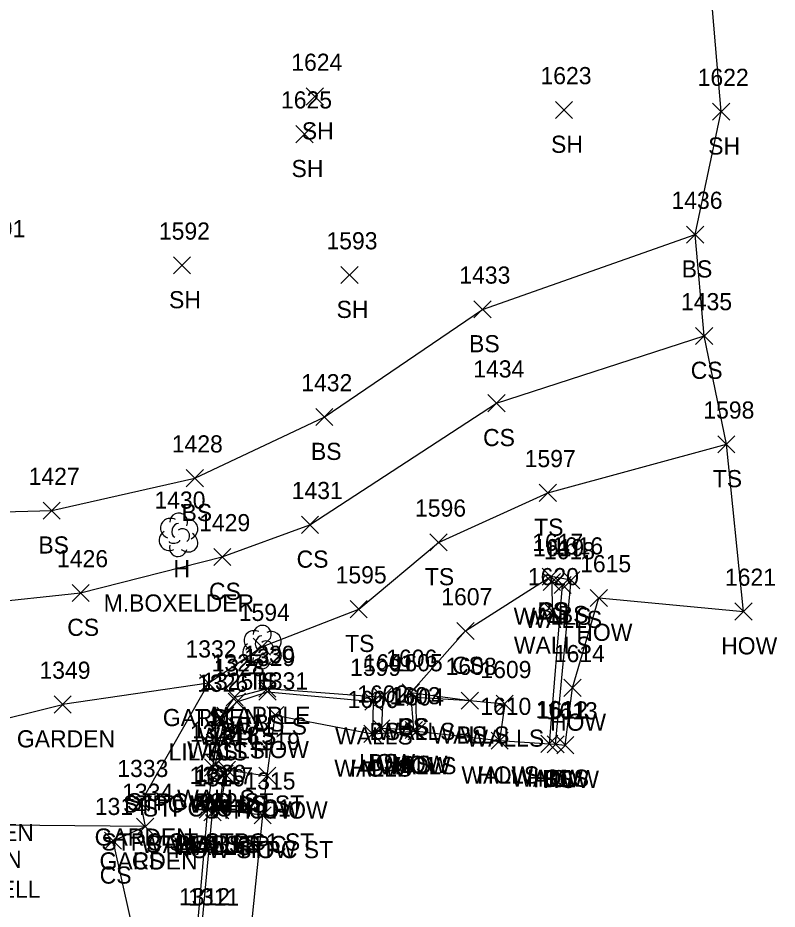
# Model space of a CAD drawing. Extents: x 1459992 to 1461532, y 647785 to 648535.
# Drawn here: x 1461426.2 to 1461514.7, y 648133.4 to 648237.3 of the extents above; entities that cross this region are included whole.
import ezdxf

# ---------------------------------------------------------------- set-up
doc = ezdxf.new("R2010")
doc.units = 0
for name, color, linetype in [('L_A', 7, 'Continuous'), ('L_C', 7, 'Continuous'), ('L_I', 7, 'Continuous'), ('L_TIC', 7, 'Continuous'), ('LAPB', 7, 'Continuous'), ('LBC', 7, 'Continuous'), ('LBF', 7, 'Continuous'), ('LELB', 7, 'Continuous'), ('LSOGP', 7, 'Continuous'), ('LTD', 7, 'Continuous'), ('LWS', 7, 'Continuous')]:
    doc.layers.add(name, color=color, linetype=linetype)

msp = doc.modelspace()

# ---------------------------------------------------------------- linework, layer by layer
at = {"layer": 'L_TIC'}
for points in [[(1461459.79, 648227.13), (1461461.79, 648229.13)], [(1461461.79, 648227.13), (1461459.79, 648229.13)], [(1461488.83, 648225.57), (1461490.83, 648227.57)], [(1461490.83, 648225.57), (1461488.83, 648227.57)], [(1461507.15, 648225.37), (1461509.15, 648227.37)], [(1461509.15, 648225.37), (1461507.15, 648227.37)], [(1461458.59, 648222.74), (1461460.59, 648224.74)], [(1461460.59, 648222.74), (1461458.59, 648224.74)], [(1461504.11, 648211.04), (1461506.11, 648213.04)], [(1461506.11, 648211.04), (1461504.11, 648213.04)], [(1461444.31, 648207.45), (1461446.31, 648209.45)], [(1461446.31, 648207.45), (1461444.31, 648209.45)], [(1461463.84, 648206.32), (1461465.84, 648208.32)], [(1461465.84, 648206.32), (1461463.84, 648208.32)], [(1461479.33, 648202.32), (1461481.33, 648204.32)], [(1461481.33, 648202.32), (1461479.33, 648204.32)], [(1461505.16, 648199.22), (1461507.16, 648201.22)], [(1461507.16, 648199.22), (1461505.16, 648201.22)], [(1461480.96, 648191.38), (1461482.96, 648193.38)], [(1461482.96, 648191.38), (1461480.96, 648193.38)], [(1461460.9, 648189.77), (1461462.9, 648191.77)], [(1461462.9, 648189.77), (1461460.9, 648191.77)], [(1461507.76, 648186.59), (1461509.76, 648188.59)], [(1461509.76, 648186.59), (1461507.76, 648188.59)], [(1461445.81, 648182.64), (1461447.81, 648184.64)], [(1461447.81, 648182.64), (1461445.81, 648184.64)], [(1461486.94, 648180.93), (1461488.94, 648182.93)], [(1461488.94, 648180.93), (1461486.94, 648182.93)], [(1461429.13, 648178.86), (1461431.13, 648180.86)], [(1461431.13, 648178.86), (1461429.13, 648180.86)], [(1461459.23, 648177.21), (1461461.23, 648179.21)], [(1461461.23, 648177.21), (1461459.23, 648179.21)], [(1461474.21, 648175.16), (1461476.21, 648177.16)], [(1461476.21, 648175.16), (1461474.21, 648177.16)], [(1461449.01, 648173.46), (1461451.01, 648175.46)], [(1461451.01, 648173.46), (1461449.01, 648175.46)], [(1461487.3, 648171.17), (1461489.3, 648173.17)], [(1461489.3, 648171.17), (1461487.3, 648173.17)], [(1461487.3, 648171.17), (1461489.3, 648173.17)], [(1461489.3, 648171.17), (1461487.3, 648173.17)], [(1461487.41, 648170.55), (1461489.41, 648172.55)], [(1461489.41, 648170.55), (1461487.41, 648172.55)], [(1461488.67, 648170.19), (1461490.67, 648172.19)], [(1461490.67, 648170.19), (1461488.67, 648172.19)], [(1461489.67, 648170.75), (1461491.67, 648172.75)], [(1461491.67, 648170.75), (1461489.67, 648172.75)], [(1461432.5, 648169.26), (1461434.5, 648171.26)], [(1461434.5, 648169.26), (1461432.5, 648171.26)], [(1461492.89, 648168.68), (1461494.89, 648170.68)], [(1461494.89, 648168.68), (1461492.89, 648170.68)], [(1461464.91, 648167.38), (1461466.91, 648169.38)], [(1461466.91, 648167.38), (1461464.91, 648169.38)], [(1461487.45, 648167.17), (1461489.45, 648169.17)], [(1461489.45, 648167.17), (1461487.45, 648169.17)], [(1461509.76, 648167.1), (1461511.76, 648169.1)], [(1461511.76, 648167.1), (1461509.76, 648169.1)], [(1461477.35, 648164.83), (1461479.35, 648166.83)], [(1461479.35, 648164.83), (1461477.35, 648166.83)], [(1461453.62, 648163), (1461455.62, 648165)], [(1461455.62, 648163), (1461453.62, 648165)], [(1461447.41, 648158.74), (1461449.41, 648160.74)], [(1461449.41, 648158.74), (1461447.41, 648160.74)], [(1461447.41, 648158.74), (1461449.41, 648160.74)], [(1461449.41, 648158.74), (1461447.41, 648160.74)], [(1461447.41, 648158.74), (1461449.41, 648160.74)], [(1461449.41, 648158.74), (1461447.41, 648160.74)], [(1461454.26, 648158.11), (1461456.26, 648160.11)], [(1461456.26, 648158.11), (1461454.26, 648160.11)], [(1461454.27, 648157.75), (1461456.27, 648159.75)], [(1461456.27, 648157.75), (1461454.27, 648159.75)], [(1461470.99, 648157.66), (1461472.99, 648159.66)], [(1461472.99, 648157.66), (1461470.99, 648159.66)], [(1461470.99, 648157.66), (1461472.99, 648159.66)], [(1461472.99, 648157.66), (1461470.99, 648159.66)], [(1461489.82, 648158.2), (1461491.82, 648160.2)], [(1461491.82, 648158.2), (1461489.82, 648160.2)], [(1461450.46, 648157.12), (1461452.46, 648159.12)], [(1461452.46, 648157.12), (1461450.46, 648159.12)], [(1461450.7, 648156.58), (1461452.7, 648158.58)], [(1461452.7, 648156.58), (1461450.7, 648158.58)], [(1461466.61, 648156.6), (1461468.61, 648158.6)], [(1461468.61, 648156.6), (1461466.61, 648158.6)], [(1461467.71, 648157.12), (1461469.71, 648159.12)], [(1461469.71, 648157.12), (1461467.71, 648159.12)], [(1461471.56, 648157.13), (1461473.56, 648159.13)], [(1461473.56, 648157.13), (1461471.56, 648159.13)], [(1461477.85, 648156.71), (1461479.85, 648158.71)], [(1461479.85, 648156.71), (1461477.85, 648158.71)], [(1461477.85, 648156.71), (1461479.85, 648158.71)], [(1461479.85, 648156.71), (1461477.85, 648158.71)], [(1461430.4, 648156.26), (1461432.4, 648158.26)], [(1461432.4, 648156.26), (1461430.4, 648158.26)], [(1461430.4, 648156.26), (1461432.4, 648158.26)], [(1461432.4, 648156.26), (1461430.4, 648158.26)], [(1461481.92, 648156.34), (1461483.92, 648158.34)], [(1461483.92, 648156.34), (1461481.92, 648158.34)], [(1461448.82, 648154.75), (1461450.82, 648156.75)], [(1461450.82, 648154.75), (1461448.82, 648156.75)], [(1461449.36, 648154.97), (1461451.36, 648156.97)], [(1461451.36, 648154.97), (1461449.36, 648156.97)], [(1461455.19, 648155.01), (1461457.19, 648157.01)], [(1461457.19, 648155.01), (1461455.19, 648157.01)], [(1461467.55, 648153.49), (1461469.55, 648155.49)], [(1461469.55, 648153.49), (1461467.55, 648155.49)], [(1461467.55, 648153.49), (1461469.55, 648155.49)], [(1461469.55, 648153.49), (1461467.55, 648155.49)], [(1461466.52, 648152.85), (1461468.52, 648154.85)], [(1461468.52, 648152.85), (1461466.52, 648154.85)], [(1461466.52, 648152.85), (1461468.52, 648154.85)], [(1461468.52, 648152.85), (1461466.52, 648154.85)], [(1461471.34, 648153.29), (1461473.34, 648155.29)], [(1461473.34, 648153.29), (1461471.34, 648155.29)], [(1461471.34, 648153.29), (1461473.34, 648155.29)], [(1461473.34, 648153.29), (1461471.34, 648155.29)], [(1461471.69, 648153.14), (1461473.69, 648155.14)], [(1461473.69, 648153.14), (1461471.69, 648155.14)], [(1461471.69, 648153.14), (1461473.69, 648155.14)], [(1461473.69, 648153.14), (1461471.69, 648155.14)], [(1461481.33, 648152.05), (1461483.33, 648154.05)], [(1461483.33, 648152.05), (1461481.33, 648154.05)], [(1461481.33, 648152.05), (1461483.33, 648154.05)], [(1461483.33, 648152.05), (1461481.33, 648154.05)], [(1461487.13, 648151.67), (1461489.13, 648153.67)], [(1461489.13, 648151.67), (1461487.13, 648153.67)], [(1461487.13, 648151.67), (1461489.13, 648153.67)], [(1461489.13, 648151.67), (1461487.13, 648153.67)], [(1461487.86, 648151.62), (1461489.86, 648153.62)], [(1461489.86, 648151.62), (1461487.86, 648153.62)], [(1461487.86, 648151.62), (1461489.86, 648153.62)], [(1461489.86, 648151.62), (1461487.86, 648153.62)], [(1461488.98, 648151.53), (1461490.98, 648153.53)], [(1461490.98, 648151.53), (1461488.98, 648153.53)], [(1461448.21, 648149.32), (1461450.21, 648151.32)], [(1461450.21, 648149.32), (1461448.21, 648151.32)], [(1461447.92, 648148.92), (1461449.92, 648150.92)], [(1461449.92, 648148.92), (1461447.92, 648150.92)], [(1461447.92, 648148.92), (1461449.92, 648150.92)], [(1461449.92, 648148.92), (1461447.92, 648150.92)], [(1461449.53, 648148.66), (1461451.53, 648150.66)], [(1461451.53, 648148.66), (1461449.53, 648150.66)], [(1461449.53, 648148.66), (1461451.53, 648150.66)], [(1461451.53, 648148.66), (1461449.53, 648150.66)], [(1461449.26, 648148.2), (1461451.26, 648150.2)], [(1461451.26, 648148.2), (1461449.26, 648150.2)], [(1461449.26, 648148.2), (1461451.26, 648150.2)], [(1461451.26, 648148.2), (1461449.26, 648150.2)], [(1461454.25, 648147.96), (1461456.25, 648149.96)], [(1461456.25, 648147.96), (1461454.25, 648149.96)], [(1461454.25, 648147.96), (1461456.25, 648149.96)], [(1461456.25, 648147.96), (1461454.25, 648149.96)], [(1461439.46, 648144.81), (1461441.46, 648146.81)], [(1461441.46, 648144.81), (1461439.46, 648146.81)], [(1461448.63, 648144.24), (1461450.63, 648146.24)], [(1461450.63, 648144.24), (1461448.63, 648146.24)], [(1461448.63, 648144.24), (1461450.63, 648146.24)], [(1461450.63, 648144.24), (1461448.63, 648146.24)], [(1461447.32, 648144), (1461449.32, 648146)], [(1461449.32, 648144), (1461447.32, 648146)], [(1461447.32, 648144), (1461449.32, 648146)], [(1461449.32, 648144), (1461447.32, 648146)], [(1461447.86, 648143.72), (1461449.86, 648145.72)], [(1461449.86, 648143.72), (1461447.86, 648145.72)], [(1461448.77, 648143.95), (1461450.77, 648145.95)], [(1461450.77, 648143.95), (1461448.77, 648145.95)], [(1461448.77, 648143.95), (1461450.77, 648145.95)], [(1461450.77, 648143.95), (1461448.77, 648145.95)], [(1461453.72, 648143.35), (1461455.72, 648145.35)], [(1461455.72, 648143.35), (1461453.72, 648145.35)], [(1461453.72, 648143.35), (1461455.72, 648145.35)], [(1461455.72, 648143.35), (1461453.72, 648145.35)], [(1461440.03, 648142.03), (1461442.03, 648144.03)], [(1461442.03, 648142.03), (1461440.03, 648144.03)], [(1461440.03, 648142.03), (1461442.03, 648144.03)], [(1461442.03, 648142.03), (1461440.03, 648144.03)], [(1461436.28, 648140.38), (1461438.28, 648142.38)], [(1461438.28, 648140.38), (1461436.28, 648142.38)]]:
    msp.add_lwpolyline(points, dxfattribs=at)
at = {"layer": 'LAPB'}
for points in [[(1461448.41, 648159.74), (1461440.46, 648145.81), (1461441.03, 648143.03), (1461420.52, 648143.22), (1461421.94, 648146.34), (1461418.63, 648150), (1461411.7, 648152.37), (1461431.4, 648157.26)], [(1461448.41, 648159.74), (1461431.4, 648157.26)]]:
    msp.add_lwpolyline(points, dxfattribs=at)
at = {"layer": 'LBC'}
msp.add_lwpolyline([(1461484.77, 648116.97), (1461480.83, 648117.3), (1461480.01, 648117.42), (1461452.25, 648119.97), (1461454.72, 648144.35), (1461455.25, 648148.96), (1461456.19, 648156.01), (1461467.52, 648153.85), (1461468.55, 648154.49), (1461472.34, 648154.29), (1461472.69, 648154.14), (1461482.33, 648153.05), (1461488.13, 648152.67), (1461488.86, 648152.62), (1461489.98, 648152.53), (1461490.82, 648159.2), (1461493.89, 648169.68), (1461510.76, 648168.1)], dxfattribs=at)
at = {"layer": 'LBF'}
for points in [[(1461449.63, 648145.24), (1461448.32, 648145), (1461448.92, 648149.92), (1461450.26, 648149.2)], [(1461454.72, 648144.35), (1461449.77, 648144.95), (1461450.53, 648149.66), (1461455.25, 648148.96)], [(1461449.63, 648145.24), (1461450.26, 648149.2)]]:
    msp.add_lwpolyline(points, dxfattribs=at)
at = {"layer": 'LELB'}
for points in [[(1461384.11, 648176.46), (1461406.23, 648179.2), (1461430.13, 648179.86), (1461446.81, 648183.64), (1461461.9, 648190.77), (1461480.33, 648203.32), (1461505.11, 648212.04)], [(1461400, 648157.98), (1461410.21, 648167.8), (1461433.5, 648170.26), (1461450.01, 648174.46), (1461460.23, 648178.21), (1461481.96, 648192.38), (1461506.16, 648200.22)], [(1461448.41, 648159.74), (1461454.62, 648164), (1461465.91, 648168.38), (1461475.21, 648176.16), (1461487.94, 648181.93), (1461508.76, 648187.59)], [(1461471.99, 648158.66), (1461478.35, 648165.83), (1461488.3, 648172.17)], [(1461488.86, 648152.62), (1461490.67, 648171.75), (1461488.3, 648172.17)], [(1461448.92, 648149.92), (1461449.82, 648155.75), (1461451.46, 648158.12), (1461455.26, 648159.11), (1461468.71, 648158.12), (1461468.55, 648154.49)], [(1461472.34, 648154.29), (1461471.99, 648158.66), (1461478.85, 648157.71)], [(1461478.64, 648106.26), (1461475.36, 648109.38), (1461473.41, 648110.98), (1461470.64, 648111.21), (1461444.9, 648114.25), (1461447.09, 648130.85), (1461448.32, 648145)], [(1461444.9, 648114.25), (1461440.28, 648127.98), (1461437.28, 648141.38), (1461441.03, 648143.03)]]:
    msp.add_lwpolyline(points, dxfattribs=at)
at = {"layer": 'LSOGP'}
msp.add_lwpolyline([(1461452.25, 648119.97), (1461454.72, 648144.35), (1461455.25, 648148.96), (1461456.19, 648156.01), (1461467.52, 648153.85), (1461472.69, 648154.14), (1461482.33, 648153.05), (1461488.13, 648152.67), (1461488.86, 648152.62), (1461489.98, 648152.53), (1461490.82, 648159.2), (1461493.89, 648169.68), (1461510.76, 648168.1), (1461508.76, 648187.59), (1461506.16, 648200.22), (1461505.11, 648212.04), (1461508.15, 648226.37), (1461506.28, 648248.38)], dxfattribs=at)
at = {"layer": 'LTD'}
for p, q in [((1461444.88, 648177.09), (1461444.88, 648177.09)), ((1461444.88, 648177.09), (1461444.88, 648177.09)), ((1461454.62, 648164), (1461454.62, 648164)), ((1461454.62, 648164), (1461454.62, 648164))]:
    msp.add_line(p, q, dxfattribs=at)
for centre in [(1461444.93, 648178.52), (1461454.67, 648165.44)]:
    msp.add_arc(centre, 1.05, 335.5272, 180.9563, dxfattribs=at)
for centre, major_axis, ratio, start_param, end_param in [((1461444.09, 648177.76), (1.21, -0.51), 0.895232, 1.570796, 4.712389), ((1461444.68, 648177.55), (-0.208, -0.792), 0.645439, 3.141593, 6.283185), ((1461445.93, 648177.67), (-1.14, -0.48), 0.949671, 1.570796, 4.712389), ((1461443.8, 648176.38), (0.58, -1.04), 0.959034, 3.141593, 6.283185), ((1461445.38, 648176.92), (-0.5, 0.667), 0.989748, 3.141593, 6.283185), ((1461444.43, 648176.34), (-0.625, -0.083), 0.423636, 0, 3.141593), ((1461445.88, 648176.26), (-1.09, 0.79), 0.841452, 1.570796, 4.712389), ((1461444.88, 648175.59), (0.26, 1.06), 0.942809, 1.570796, 4.712389), ((1461453.83, 648164.67), (1.21, -0.51), 0.895232, 1.570796, 4.712389), ((1461455.66, 648164.59), (-1.14, -0.48), 0.949671, 1.570796, 4.712389), ((1461454.41, 648164.46), (-0.208, -0.792), 0.645439, 3.141593, 6.283185), ((1461453.54, 648163.29), (0.58, -1.04), 0.959034, 3.141593, 6.283185), ((1461455.12, 648163.84), (-0.5, 0.667), 0.989748, 3.141593, 6.283185), ((1461455.62, 648163.17), (-1.09, 0.79), 0.841452, 1.570796, 4.712389), ((1461454.62, 648162.5), (0.26, 1.06), 0.942809, 1.570796, 4.712389), ((1461454.16, 648163.25), (-0.625, -0.083), 0.423636, 0, 3.141593)]:
    msp.add_ellipse(centre, major_axis=major_axis, ratio=ratio, start_param=start_param, end_param=end_param, dxfattribs=at)
at = {"layer": 'LWS'}
for points in [[(1461488.13, 648152.67), (1461489.67, 648171.19), (1461488.41, 648171.55), (1461488.45, 648168.17)], [(1461450.53, 648149.66), (1461449.21, 648150.32), (1461450.36, 648155.97), (1461451.7, 648157.58), (1461455.27, 648158.75), (1461467.61, 648157.6), (1461467.52, 648153.85)], [(1461472.69, 648154.14), (1461472.56, 648158.13), (1461478.85, 648157.71), (1461482.92, 648157.34), (1461482.33, 648153.05)], [(1461470.92, 648111.93), (1461445.55, 648114.71), (1461447.59, 648130.83), (1461448.86, 648144.72), (1461449.77, 648144.95)]]:
    msp.add_lwpolyline(points, dxfattribs=at)

# ---------------------------------------------------------------- texts
at = {"layer": 'L_A'}
for s, p in [('SH', (1461459.28, 648223.13)), ('SH', (1461488.32, 648221.57)), ('SH', (1461506.64, 648221.37)), ('SH', (1461458.08, 648218.74)), ('BS', (1461503.55, 648207.04)), ('SH', (1461443.8, 648203.45)), ('SH', (1461463.33, 648202.32)), ('BS', (1461478.77, 648198.32)), ('CS', (1461504.6, 648195.22)), ('CS', (1461480.4, 648187.38)), ('BS', (1461460.34, 648185.77)), ('TS', (1461507.17, 648182.59)), ('BS', (1461445.26, 648178.64)), ('TS', (1461486.35, 648176.93)), ('BS', (1461428.57, 648174.86)), ('CS', (1461458.67, 648173.21)), ('H', (1461444.32, 648172.09)), ('TS', (1461473.62, 648171.16)), ('CS', (1461448.46, 648169.46)), ('CS', (1461486.74, 648167.17)), ('BS', (1461486.74, 648167.17)), ('WALLS', (1461483.96, 648166.55)), ('WALLS', (1461485.21, 648166.19)), ('BS', (1461489.11, 648166.75)), ('CS', (1461431.94, 648165.26)), ('HOW', (1461491.27, 648164.68)), ('TS', (1461464.32, 648163.38)), ('WALLS', (1461483.99, 648163.17)), ('HOW', (1461508.15, 648163.1)), ('CS', (1461476.79, 648160.83)), ('TS', (1461453.03, 648159)), ('H', (1461454.05, 648159)), ('GARDEN', (1461443.08, 648154.74)), ('GARDEN', (1461443.08, 648154.74)), ('TS', (1461446.82, 648154.74)), ('WALLS', (1461450.81, 648153.75)), ('BS', (1461453.7, 648154.11)), ('CS', (1461470.43, 648153.66)), ('BS', (1461470.43, 648153.66)), ('HOW', (1461488.2, 648154.2)), ('WALLS', (1461447.24, 648152.58)), ('BS', (1461449.9, 648153.12)), ('WALLS', (1461463.15, 648152.6)), ('BS', (1461467.15, 648153.12)), ('WALLS', (1461468.11, 648153.13)), ('WALLS', (1461474.4, 648152.71)), ('BS', (1461477.29, 648152.71)), ('GARDEN', (1461426.07, 648152.26)), ('GARDEN', (1461426.07, 648152.26)), ('WALLS', (1461478.46, 648152.34)), ('WALLS', (1461445.91, 648150.97)), ('BS', (1461448.26, 648150.75)), ('HOW', (1461453.57, 648151.01)), ('HOW', (1461465.94, 648149.49)), ('BS', (1461466.99, 648149.49)), ('HOW', (1461469.73, 648149.29)), ('BS', (1461470.78, 648149.29)), ('WALLS', (1461463.06, 648148.85)), ('HOW', (1461464.9, 648148.85)), ('WALLS', (1461468.24, 648149.14)), ('HOW', (1461470.08, 648149.14)), ('WALLS', (1461477.88, 648148.05)), ('HOW', (1461479.72, 648148.05)), ('WALLS', (1461483.68, 648147.67)), ('HOW', (1461485.52, 648147.67)), ('HOW', (1461486.24, 648147.62)), ('BS', (1461487.3, 648147.62)), ('HOW', (1461487.37, 648147.53)), ('WALLS', (1461444.75, 648145.32)), ('STPC WALLS ST', (1461438.44, 648144.66)), ('STPC BS2 ST', (1461438.88, 648144.92)), ('STPC  STPC1', (1461440.75, 648144.2)), ('STPC  STPC1', (1461440.75, 648144.2)), ('WALLS', (1461446.07, 648144.66)), ('BS', (1461447.36, 648144.92)), ('STPC HOW', (1461447.88, 648143.96)), ('HOW', (1461452.64, 648143.96)), ('GARDEN', (1461416.61, 648141.34)), ('GARDEN', (1461435.13, 648140.81)), ('STPC ST STPC1 ST', (1461435.91, 648140.24)), ('STPC ST STPC1 ST', (1461435.91, 648140.24)), ('WALLS STPC', (1461440.55, 648139.95)), ('STPC BS2', (1461441.11, 648140)), ('WALLS', (1461445.31, 648139.95)), ('BS', (1461446.76, 648140)), ('WALLS', (1461444.41, 648139.72)), ('HOW STPC ST', (1461444.35, 648139.35)), ('HOW', (1461452.1, 648139.35)), ('GARDEN', (1461415.19, 648138.22)), ('GARDEN', (1461435.7, 648138.03)), ('CS', (1461439.47, 648138.03)), ('CS', (1461435.72, 648136.38))]:
    msp.add_text(s, height=2, dxfattribs=at).set_placement(p)
at = {"layer": 'L_C'}
for s, p in [('M.BOXELDER', (1461436.18, 648168.09)), ('M.APPLE', (1461448.68, 648155)), ('LILACS', (1461443.75, 648150.74)), ('LILACS', (1461443.75, 648150.74)), ('OLD STN WELL', (1461409.21, 648134.73)), ('OLD STN WELL', (1461409.21, 648134.73))]:
    msp.add_text(s, height=2, dxfattribs=at).set_placement(p)
at = {"layer": 'L_I'}
for s, p in [('1624', (1461458.05, 648231.13)), ('1623', (1461487.09, 648229.57)), ('1622', (1461505.41, 648229.37)), ('1625', (1461456.85, 648226.74)), ('1436', (1461502.36, 648215.04)), ('1591', (1461421.11, 648211.73)), ('1592', (1461442.62, 648211.45)), ('1593', (1461462.15, 648210.32)), ('1433', (1461477.63, 648206.32)), ('1435', (1461503.47, 648203.22)), ('1434', (1461479.26, 648195.38)), ('1432', (1461459.21, 648193.77)), ('1598', (1461506.07, 648190.59)), ('1428', (1461444.12, 648186.64)), ('1597', (1461485.25, 648184.93)), ('1427', (1461427.44, 648182.86)), ('1431', (1461458.1, 648181.21)), ('1430', (1461442.1, 648180.09)), ('1596', (1461472.47, 648179.16)), ('1429', (1461447.31, 648177.46)), ('1617', (1461486.12, 648175.17)), ('1617', (1461486.12, 648175.17)), ('1619', (1461486.23, 648174.55)), ('1616', (1461488.44, 648174.75)), ('1426', (1461430.75, 648173.26)), ('1618', (1461487.49, 648174.19)), ('1615', (1461491.71, 648172.68)), ('1595', (1461463.22, 648171.38)), ('1620', (1461485.62, 648171.17)), ('1621', (1461508.59, 648171.1)), ('1607', (1461475.53, 648168.83)), ('1594', (1461451.93, 648167)), ('1594', (1461451.93, 648167)), ('1332', (1461445.72, 648162.74)), ('1332', (1461445.72, 648162.74)), ('1332', (1461445.72, 648162.74)), ('1330', (1461452.48, 648162.11)), ('1329', (1461452.57, 648161.75)), ('1614', (1461488.64, 648162.2)), ('1327', (1461448.77, 648161.12)), ('1601', (1461466.46, 648161.12)), ('1606', (1461469.11, 648161.66)), ('1606', (1461469.11, 648161.66)), ('1605', (1461469.75, 648161.13)), ('1608', (1461476.03, 648160.71)), ('1608', (1461476.03, 648160.71)), ('1349', (1461428.7, 648160.26)), ('1349', (1461428.7, 648160.26)), ('1328', (1461449, 648160.58)), ('1599', (1461464.9, 648160.6)), ('1609', (1461480.09, 648160.34)), ('1326', (1461447.08, 648158.75)), ('1325', (1461447.67, 648158.97)), ('1331', (1461454.06, 648159.01)), ('1600', (1461464.61, 648156.85)), ('1600', (1461464.61, 648156.85)), ('1602', (1461465.73, 648157.49)), ('1602', (1461465.73, 648157.49)), ('1603', (1461469.52, 648157.29)), ('1603', (1461469.52, 648157.29)), ('1604', (1461469.88, 648157.14)), ('1604', (1461469.88, 648157.14)), ('1610', (1461480.07, 648156.05)), ('1610', (1461480.07, 648156.05)), ('1611', (1461486.53, 648155.67)), ('1611', (1461486.53, 648155.67)), ('1612', (1461486.68, 648155.62)), ('1612', (1461486.68, 648155.62)), ('1613', (1461487.81, 648155.53)), ('1322', (1461446.23, 648152.92)), ('1322', (1461446.23, 648152.92)), ('1324', (1461446.52, 648153.32)), ('1318', (1461448.4, 648152.66)), ('1318', (1461448.4, 648152.66)), ('1323', (1461447.57, 648152.2)), ('1323', (1461447.57, 648152.2)), ('1319', (1461453.12, 648151.96)), ('1319', (1461453.12, 648151.96)), ('1333', (1461437.77, 648148.81)), ('1320', (1461446.85, 648148.24)), ('1320', (1461446.85, 648148.24)), ('1321', (1461446.2, 648148)), ('1321', (1461446.2, 648148)), ('1316', (1461446.68, 648147.72)), ('1317', (1461447.64, 648147.95)), ('1317', (1461447.64, 648147.95)), ('1315', (1461452.59, 648147.35)), ('1315', (1461452.59, 648147.35)), ('1334', (1461438.33, 648146.03)), ('1334', (1461438.33, 648146.03)), ('1314', (1461435.15, 648144.38)), ('1312', (1461444.96, 648133.85)), ('1311', (1461446.03, 648133.83))]:
    msp.add_text(s, height=2, dxfattribs=at).set_placement(p)

doc.saveas('drawing.dxf')
